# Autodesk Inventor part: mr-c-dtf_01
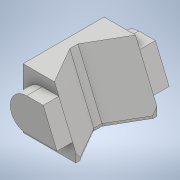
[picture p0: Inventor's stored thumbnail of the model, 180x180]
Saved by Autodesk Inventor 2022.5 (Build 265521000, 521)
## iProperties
Part Number: mr-c-dtf_01
Material: 一般
Document SubType Name: Modeling
Designer: ImaoCorp
Density: 1 g/cm^3
Appearance: 既定
Author: ImaoCorp
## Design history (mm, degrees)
feature "mr-c-dtf_01"
node "ソリッド1"
